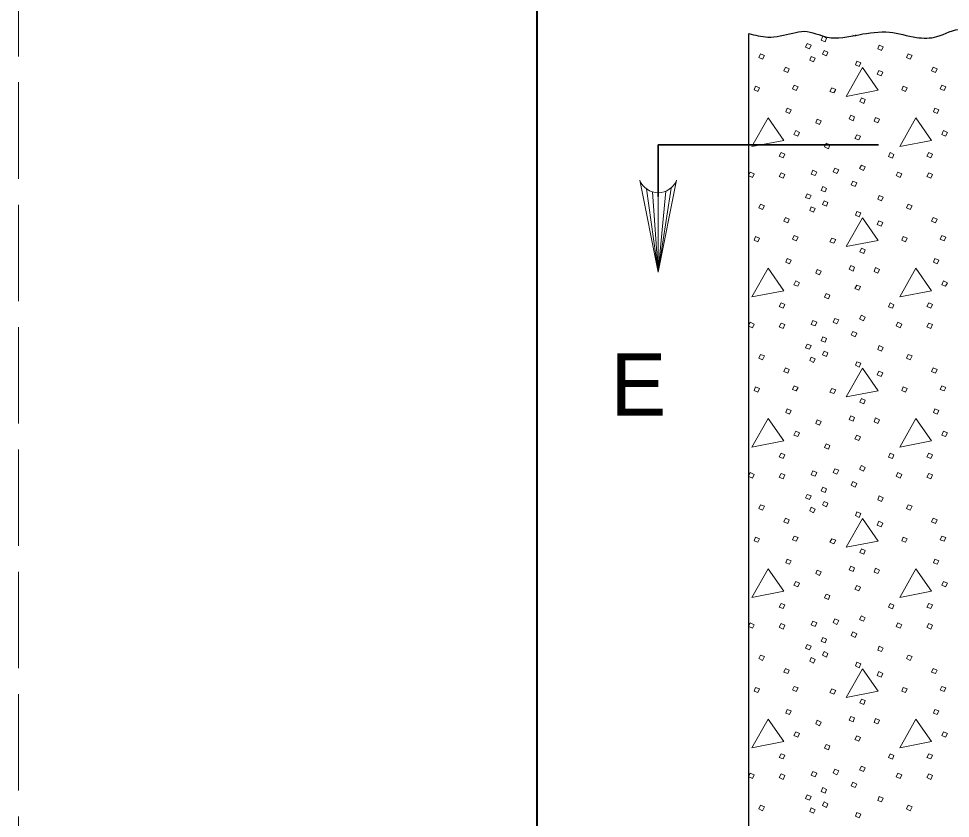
# Model space of a CAD drawing. Extents: x 1036.7 to 1070.7, y 883.9 to 905.9.
# Drawn here: x 1036.673 to 1040.267, y 896.461 to 899.546 of the extents above; entities that cross this region are included whole.
import ezdxf

# ---------------------------------------------------------------- set-up
doc = ezdxf.new("R2010")
doc.units = 0
doc.header["$LTSCALE"] = 0.062
doc.linetypes.add('LONG_DASHED', pattern=[7.5, 6, -1.5])
doc.layers.add('1', color=7, linetype='Continuous', lineweight=13)

msp = doc.modelspace()

# ---------------------------------------------------------------- linework, layer by layer
at = {"layer": '1', "lineweight": 25}
msp.add_line((1039.48992, 893.80992), (1039.48992, 899.48867), dxfattribs=at)
at = {"layer": '1', "lineweight": 35}
for q in [(1039.98967, 899.05975), (1039.14008, 898.85983)]:
    msp.add_line((1039.14008, 899.05975), q, dxfattribs=at)
at = {"layer": '1'}
for p, q in [((1039.48992, 898.94317), (1039.49467, 898.95425)), ((1039.09517, 898.88883), (1039.14008, 898.56833)), ((1039.11742, 898.878), (1039.14008, 898.56833)), ((1039.18958, 898.89258), (1039.14008, 898.56833)), ((1039.16883, 898.88033), (1039.14008, 898.56833)), ((1039.14008, 898.87467), (1039.14008, 898.56833)), ((1039.48992, 898.3635), (1039.49467, 898.37458)), ((1039.48992, 897.78383), (1039.49467, 897.79492)), ((1039.48992, 897.20417), (1039.49467, 897.21525)), ((1039.48992, 896.6245), (1039.49467, 896.63558))]:
    msp.add_line(p, q, dxfattribs=at)
at = {"layer": '1', "linetype": 'LONG_DASHED'}
msp.add_lwpolyline([(1036.67333, 883.90825), (1070.67333, 883.90825), (1070.67333, 905.90825), (1036.67333, 905.90825)], close=True, dxfattribs=at)
at = {"layer": '1', "lineweight": 25}
msp.add_lwpolyline([(1070.17333, 884.40825), (1038.67333, 884.40825), (1038.67333, 905.40825)], dxfattribs=at)
at = {"layer": '1', "lineweight": 40}
msp.add_lwpolyline([(1038.67333, 905.40825), (1070.17333, 905.40825), (1070.17333, 884.40825), (1038.67333, 884.40825)], close=True, dxfattribs=at)
msp.add_lwpolyline([(1038.67333, 905.40825), (1070.17333, 905.40825), (1070.17333, 884.40825), (1038.67333, 884.40825)], close=True, dxfattribs=at)
at = {"layer": '1'}
for points in [[(1039.7745, 899.478), (1039.7895, 899.471), (1039.7835, 899.457), (1039.7685, 899.463)], [(1039.7145, 899.45), (1039.7295, 899.444), (1039.7235, 899.43), (1039.7085, 899.436)], [(1039.99242, 899.444), (1040.00742, 899.437), (1040.00142, 899.423), (1039.98642, 899.429)], [(1039.53458, 899.41), (1039.54958, 899.404), (1039.54258, 899.389), (1039.52758, 899.396)], [(1039.7305, 899.4), (1039.7455, 899.393), (1039.7395, 899.379), (1039.7245, 899.386)], [(1039.7795, 899.423), (1039.7945, 899.416), (1039.7885, 899.402), (1039.7735, 899.409)], [(1040.10433, 899.41), (1040.11933, 899.404), (1040.11233, 899.389), (1040.09733, 899.396)], [(1039.90642, 899.382), (1039.92142, 899.376), (1039.91542, 899.36108), (1039.90042, 899.368)], [(1039.63058, 899.35808), (1039.64558, 899.35208), (1039.63958, 899.33808), (1039.62458, 899.34408)], [(1039.92742, 899.357), (1039.86542, 899.24608), (1039.98842, 899.27008)], [(1039.99142, 899.34608), (1040.00642, 899.33908), (1039.99942, 899.32508), (1039.98442, 899.33108)], [(1040.20033, 899.35808), (1040.21525, 899.35208), (1040.20925, 899.33808), (1040.19433, 899.34408)], [(1039.51558, 899.28508), (1039.53058, 899.27908), (1039.52458, 899.26508), (1039.50958, 899.27108)], [(1039.66458, 899.28908), (1039.6795, 899.28308), (1039.67258, 899.26908), (1039.65758, 899.27508)], [(1039.8095, 899.27908), (1039.8245, 899.27308), (1039.8175, 899.25908), (1039.8025, 899.26508)], [(1040.08533, 899.28508), (1040.10033, 899.27908), (1040.09433, 899.26508), (1040.07933, 899.27108)], [(1040.23425, 899.28908), (1040.24925, 899.28308), (1040.24225, 899.26908), (1040.22725, 899.27508)], [(1039.92342, 899.24008), (1039.93842, 899.23408), (1039.93242, 899.21908), (1039.91742, 899.22608)], [(1039.63758, 899.20017), (1039.65258, 899.19417), (1039.64658, 899.18017), (1039.63158, 899.18617)], [(1040.20733, 899.20017), (1040.22225, 899.19417), (1040.21625, 899.18017), (1040.20133, 899.18617)], [(1039.56358, 899.16317), (1039.50167, 899.05225), (1039.62458, 899.07617)], [(1039.7535, 899.15817), (1039.7685, 899.15117), (1039.7625, 899.13717), (1039.7475, 899.14417)], [(1039.88242, 899.17317), (1039.89742, 899.16717), (1039.89142, 899.15217), (1039.87642, 899.15917)], [(1039.97842, 899.16517), (1039.99342, 899.15817), (1039.98742, 899.14417), (1039.97242, 899.15017)], [(1040.13333, 899.16317), (1040.07133, 899.05225), (1040.19433, 899.07617)], [(1039.67058, 899.11417), (1039.6855, 899.10717), (1039.67858, 899.09317), (1039.66358, 899.09917)], [(1040.24025, 899.11417), (1040.25525, 899.10717), (1040.24825, 899.09317), (1040.23325, 899.09917)], [(1039.90542, 899.09817), (1039.92042, 899.09217), (1039.91342, 899.07817), (1039.89842, 899.08417)], [(1039.7875, 899.06525), (1039.8025, 899.05925), (1039.7965, 899.04425), (1039.7815, 899.05125)], [(1039.61358, 899.02925), (1039.62858, 899.02325), (1039.62158, 899.00925), (1039.60658, 899.01525)], [(1040.03442, 899.02925), (1040.04933, 899.02225), (1040.04333, 899.00825), (1040.02842, 899.01425)], [(1040.18333, 899.02925), (1040.19833, 899.02325), (1040.19133, 899.00925), (1040.17633, 899.01525)], [(1039.8215, 898.96925), (1039.8365, 898.96325), (1039.8295, 898.94825), (1039.8145, 898.95525)], [(1039.92342, 898.98125), (1039.93842, 898.97425), (1039.93142, 898.96025), (1039.91642, 898.96725)], [(1039.61358, 898.95125), (1039.62858, 898.94525), (1039.62158, 898.93025), (1039.60658, 898.93725)], [(1039.7365, 898.96125), (1039.7515, 898.95425), (1039.7455, 898.94025), (1039.7305, 898.94625)], [(1040.06433, 898.95425), (1040.07933, 898.94725), (1040.07333, 898.93325), (1040.05833, 898.94025)], [(1040.18333, 898.95125), (1040.19833, 898.94525), (1040.19133, 898.93025), (1040.17633, 898.93725)], [(1039.7745, 898.89833), (1039.7895, 898.89133), (1039.7835, 898.87733), (1039.7685, 898.88333)], [(1039.89042, 898.91933), (1039.90542, 898.91233), (1039.89942, 898.89833), (1039.88442, 898.90533)], [(1039.7145, 898.87033), (1039.7295, 898.86433), (1039.7235, 898.85033), (1039.7085, 898.85633)], [(1039.99242, 898.86433), (1040.00742, 898.85733), (1040.00142, 898.84333), (1039.98642, 898.84933)], [(1039.53458, 898.83033), (1039.54958, 898.82433), (1039.54258, 898.80933), (1039.52758, 898.81633)], [(1039.7795, 898.84333), (1039.7945, 898.83633), (1039.7885, 898.82233), (1039.7735, 898.82933)], [(1040.10433, 898.83033), (1040.11933, 898.82433), (1040.11233, 898.80933), (1040.09733, 898.81633)], [(1039.7305, 898.82033), (1039.7455, 898.81333), (1039.7395, 898.79933), (1039.7245, 898.80633)], [(1039.90642, 898.80233), (1039.92142, 898.79633), (1039.91542, 898.78133), (1039.90042, 898.78833)], [(1039.63058, 898.77842), (1039.64558, 898.77242), (1039.63958, 898.75842), (1039.62458, 898.76442)], [(1039.92742, 898.77742), (1039.86542, 898.66642), (1039.98842, 898.69042)], [(1039.99142, 898.76642), (1040.00642, 898.75942), (1039.99942, 898.74542), (1039.98442, 898.75142)], [(1040.20033, 898.77842), (1040.21525, 898.77242), (1040.20925, 898.75842), (1040.19433, 898.76442)], [(1039.51558, 898.70542), (1039.53058, 898.69942), (1039.52458, 898.68542), (1039.50958, 898.69142)], [(1039.66458, 898.70942), (1039.6795, 898.70342), (1039.67258, 898.68942), (1039.65758, 898.69542)], [(1039.8095, 898.69942), (1039.8245, 898.69342), (1039.8175, 898.67942), (1039.8025, 898.68542)], [(1040.08533, 898.70542), (1040.10033, 898.69942), (1040.09433, 898.68542), (1040.07933, 898.69142)], [(1040.23425, 898.70942), (1040.24925, 898.70342), (1040.24225, 898.68942), (1040.22725, 898.69542)], [(1039.92342, 898.66042), (1039.93842, 898.65442), (1039.93242, 898.63942), (1039.91742, 898.64642)], [(1039.63758, 898.6205), (1039.65258, 898.6145), (1039.64658, 898.6005), (1039.63158, 898.6065)], [(1040.20733, 898.6205), (1040.22225, 898.6145), (1040.21625, 898.6005), (1040.20133, 898.6065)], [(1039.56358, 898.5835), (1039.50167, 898.47258), (1039.62458, 898.4965)], [(1039.7535, 898.5785), (1039.7685, 898.5715), (1039.7625, 898.5575), (1039.7475, 898.5645)], [(1039.88242, 898.5935), (1039.89742, 898.5875), (1039.89142, 898.5725), (1039.87642, 898.5795)], [(1039.97842, 898.5855), (1039.99342, 898.5785), (1039.98742, 898.5645), (1039.97242, 898.5705)], [(1040.13333, 898.5835), (1040.07133, 898.47258), (1040.19433, 898.4965)], [(1039.67058, 898.5345), (1039.6855, 898.5275), (1039.67858, 898.5135), (1039.66358, 898.5195)], [(1039.90542, 898.5185), (1039.92042, 898.5125), (1039.91342, 898.4985), (1039.89842, 898.5045)], [(1040.24025, 898.5345), (1040.25525, 898.5275), (1040.24825, 898.5135), (1040.23325, 898.5195)], [(1039.7875, 898.48558), (1039.8025, 898.47958), (1039.7965, 898.46458), (1039.7815, 898.47158)], [(1039.61358, 898.44958), (1039.62858, 898.44358), (1039.62158, 898.42958), (1039.60658, 898.43558)], [(1040.03442, 898.44958), (1040.04933, 898.44258), (1040.04333, 898.42858), (1040.02842, 898.43458)], [(1040.18333, 898.44958), (1040.19833, 898.44358), (1040.19133, 898.42958), (1040.17633, 898.43558)], [(1039.92342, 898.40158), (1039.93842, 898.39458), (1039.93142, 898.38058), (1039.91642, 898.38758)], [(1039.61358, 898.37158), (1039.62858, 898.36558), (1039.62158, 898.35058), (1039.60658, 898.35758)], [(1039.7365, 898.38158), (1039.7515, 898.37458), (1039.7455, 898.36058), (1039.7305, 898.36658)], [(1039.8215, 898.38958), (1039.8365, 898.38358), (1039.8295, 898.36858), (1039.8145, 898.37558)], [(1040.06433, 898.37458), (1040.07933, 898.36758), (1040.07333, 898.35358), (1040.05833, 898.36058)], [(1040.18333, 898.37158), (1040.19833, 898.36558), (1040.19133, 898.35058), (1040.17633, 898.35758)], [(1039.89042, 898.33967), (1039.90542, 898.33267), (1039.89942, 898.31867), (1039.88442, 898.32567)], [(1039.7145, 898.29067), (1039.7295, 898.28467), (1039.7235, 898.27067), (1039.7085, 898.27667)], [(1039.7745, 898.31867), (1039.7895, 898.31167), (1039.7835, 898.29767), (1039.7685, 898.30367)], [(1039.99242, 898.28467), (1040.00742, 898.27767), (1040.00142, 898.26367), (1039.98642, 898.26967)], [(1039.53458, 898.25067), (1039.54958, 898.24467), (1039.54258, 898.22967), (1039.52758, 898.23667)], [(1039.7795, 898.26367), (1039.7945, 898.25667), (1039.7885, 898.24267), (1039.7735, 898.24967)], [(1040.10433, 898.25067), (1040.11933, 898.24467), (1040.11233, 898.22967), (1040.09733, 898.23667)], [(1039.7305, 898.24067), (1039.7455, 898.23367), (1039.7395, 898.21967), (1039.7245, 898.22667)], [(1039.90642, 898.22267), (1039.92142, 898.21667), (1039.91542, 898.20167), (1039.90042, 898.20867)], [(1039.63058, 898.19875), (1039.64558, 898.19275), (1039.63958, 898.17875), (1039.62458, 898.18475)], [(1039.92742, 898.19775), (1039.86542, 898.08675), (1039.98842, 898.11075)], [(1039.99142, 898.18675), (1040.00642, 898.17975), (1039.99942, 898.16575), (1039.98442, 898.17175)], [(1040.20033, 898.19875), (1040.21525, 898.19275), (1040.20925, 898.17875), (1040.19433, 898.18475)], [(1039.51558, 898.12575), (1039.53058, 898.11975), (1039.52458, 898.10575), (1039.50958, 898.11175)], [(1039.66458, 898.12975), (1039.6795, 898.12375), (1039.67258, 898.10975), (1039.65758, 898.11575)], [(1039.8095, 898.11975), (1039.8245, 898.11375), (1039.8175, 898.09975), (1039.8025, 898.10575)], [(1040.08533, 898.12575), (1040.10033, 898.11975), (1040.09433, 898.10575), (1040.07933, 898.11175)], [(1040.23425, 898.12975), (1040.24925, 898.12375), (1040.24225, 898.10975), (1040.22725, 898.11575)], [(1039.92342, 898.08075), (1039.93842, 898.07475), (1039.93242, 898.05975), (1039.91742, 898.06675)], [(1039.63758, 898.04083), (1039.65258, 898.03483), (1039.64658, 898.02083), (1039.63158, 898.02683)], [(1040.20733, 898.04083), (1040.22225, 898.03483), (1040.21625, 898.02083), (1040.20133, 898.02683)], [(1039.56358, 898.00383), (1039.50167, 897.89292), (1039.62458, 897.91683)], [(1039.7535, 897.99883), (1039.7685, 897.99183), (1039.7625, 897.97783), (1039.7475, 897.98483)], [(1039.88242, 898.01383), (1039.89742, 898.00783), (1039.89142, 897.99283), (1039.87642, 897.99983)], [(1039.97842, 898.00583), (1039.99342, 897.99883), (1039.98742, 897.98483), (1039.97242, 897.99083)], [(1040.13333, 898.00383), (1040.07133, 897.89292), (1040.19433, 897.91683)], [(1039.67058, 897.95483), (1039.6855, 897.94783), (1039.67858, 897.93383), (1039.66358, 897.93983)], [(1039.90542, 897.93883), (1039.92042, 897.93283), (1039.91342, 897.91883), (1039.89842, 897.92483)], [(1040.24025, 897.95483), (1040.25525, 897.94783), (1040.24825, 897.93383), (1040.23325, 897.93983)], [(1039.7875, 897.90592), (1039.8025, 897.89992), (1039.7965, 897.88492), (1039.7815, 897.89192)], [(1039.61358, 897.86992), (1039.62858, 897.86392), (1039.62158, 897.84992), (1039.60658, 897.85592)], [(1040.03442, 897.86992), (1040.04933, 897.86292), (1040.04333, 897.84892), (1040.02842, 897.85492)], [(1040.18333, 897.86992), (1040.19833, 897.86392), (1040.19133, 897.84992), (1040.17633, 897.85592)], [(1039.92342, 897.82192), (1039.93842, 897.81492), (1039.93142, 897.80092), (1039.91642, 897.80792)], [(1039.61358, 897.79192), (1039.62858, 897.78592), (1039.62158, 897.77092), (1039.60658, 897.77792)], [(1039.7365, 897.80192), (1039.7515, 897.79492), (1039.7455, 897.78092), (1039.7305, 897.78692)], [(1039.8215, 897.80992), (1039.8365, 897.80392), (1039.8295, 897.78892), (1039.8145, 897.79592)], [(1040.06433, 897.79492), (1040.07933, 897.78792), (1040.07333, 897.77392), (1040.05833, 897.78092)], [(1040.18333, 897.79192), (1040.19833, 897.78592), (1040.19133, 897.77092), (1040.17633, 897.77792)], [(1039.89042, 897.76), (1039.90542, 897.753), (1039.89942, 897.739), (1039.88442, 897.746)], [(1039.7145, 897.711), (1039.7295, 897.705), (1039.7235, 897.691), (1039.7085, 897.697)], [(1039.7745, 897.739), (1039.7895, 897.732), (1039.7835, 897.718), (1039.7685, 897.724)], [(1039.7795, 897.684), (1039.7945, 897.677), (1039.7885, 897.663), (1039.7735, 897.67)], [(1039.99242, 897.705), (1040.00742, 897.698), (1040.00142, 897.684), (1039.98642, 897.69)], [(1039.53458, 897.671), (1039.54958, 897.665), (1039.54258, 897.65), (1039.52758, 897.657)], [(1039.7305, 897.661), (1039.7455, 897.654), (1039.7395, 897.64), (1039.7245, 897.647)], [(1039.90642, 897.643), (1039.92142, 897.637), (1039.91542, 897.62208), (1039.90042, 897.629)], [(1040.10433, 897.671), (1040.11933, 897.665), (1040.11233, 897.65), (1040.09733, 897.657)], [(1039.63058, 897.61908), (1039.64558, 897.61308), (1039.63958, 897.59908), (1039.62458, 897.60508)], [(1039.92742, 897.61808), (1039.86542, 897.50708), (1039.98842, 897.53108)], [(1039.99142, 897.60708), (1040.00642, 897.60008), (1039.99942, 897.58608), (1039.98442, 897.59208)], [(1040.20033, 897.61908), (1040.21525, 897.61308), (1040.20925, 897.59908), (1040.19433, 897.60508)], [(1039.51558, 897.54608), (1039.53058, 897.54008), (1039.52458, 897.52608), (1039.50958, 897.53208)], [(1039.66458, 897.55008), (1039.6795, 897.54408), (1039.67258, 897.53008), (1039.65758, 897.53608)], [(1039.8095, 897.54008), (1039.8245, 897.53408), (1039.8175, 897.52008), (1039.8025, 897.52608)], [(1040.08533, 897.54608), (1040.10033, 897.54008), (1040.09433, 897.52608), (1040.07933, 897.53208)], [(1040.23425, 897.55008), (1040.24925, 897.54408), (1040.24225, 897.53008), (1040.22725, 897.53608)], [(1039.92342, 897.50108), (1039.93842, 897.49508), (1039.93242, 897.48017), (1039.91742, 897.48708)], [(1039.63758, 897.46117), (1039.65258, 897.45517), (1039.64658, 897.44117), (1039.63158, 897.44717)], [(1040.20733, 897.46117), (1040.22225, 897.45517), (1040.21625, 897.44117), (1040.20133, 897.44717)], [(1039.56358, 897.42417), (1039.50167, 897.31325), (1039.62458, 897.33717)], [(1039.88242, 897.43417), (1039.89742, 897.42817), (1039.89142, 897.41317), (1039.87642, 897.42017)], [(1039.97842, 897.42617), (1039.99342, 897.41917), (1039.98742, 897.40517), (1039.97242, 897.41117)], [(1040.13333, 897.42417), (1040.07133, 897.31325), (1040.19433, 897.33717)], [(1039.7535, 897.41917), (1039.7685, 897.41217), (1039.7625, 897.39817), (1039.7475, 897.40517)], [(1039.67058, 897.37517), (1039.6855, 897.36817), (1039.67858, 897.35417), (1039.66358, 897.36017)], [(1039.90542, 897.35917), (1039.92042, 897.35317), (1039.91342, 897.33917), (1039.89842, 897.34517)], [(1040.24025, 897.37517), (1040.25525, 897.36817), (1040.24825, 897.35417), (1040.23325, 897.36017)], [(1039.7875, 897.32625), (1039.8025, 897.32025), (1039.7965, 897.30525), (1039.7815, 897.31225)], [(1039.61358, 897.29025), (1039.62858, 897.28425), (1039.62158, 897.27025), (1039.60658, 897.27625)], [(1040.03442, 897.29025), (1040.04933, 897.28325), (1040.04333, 897.26925), (1040.02842, 897.27525)], [(1040.18333, 897.29025), (1040.19833, 897.28425), (1040.19133, 897.27025), (1040.17633, 897.27625)], [(1039.92342, 897.24225), (1039.93842, 897.23525), (1039.93142, 897.22125), (1039.91642, 897.22825)], [(1039.61358, 897.21225), (1039.62858, 897.20625), (1039.62158, 897.19125), (1039.60658, 897.19825)], [(1039.7365, 897.22225), (1039.7515, 897.21525), (1039.7455, 897.20125), (1039.7305, 897.20725)], [(1039.8215, 897.23025), (1039.8365, 897.22425), (1039.8295, 897.20925), (1039.8145, 897.21625)], [(1040.06433, 897.21525), (1040.07933, 897.20825), (1040.07333, 897.19425), (1040.05833, 897.20125)], [(1040.18333, 897.21225), (1040.19833, 897.20625), (1040.19133, 897.19125), (1040.17633, 897.19825)], [(1039.89042, 897.18033), (1039.90542, 897.17333), (1039.89942, 897.15933), (1039.88442, 897.16633)], [(1039.7745, 897.15933), (1039.7895, 897.15233), (1039.7835, 897.13833), (1039.7685, 897.14433)], [(1039.7145, 897.13133), (1039.7295, 897.12533), (1039.7235, 897.11133), (1039.7085, 897.11733)], [(1039.7795, 897.10433), (1039.7945, 897.09733), (1039.7885, 897.08333), (1039.7735, 897.09033)], [(1039.99242, 897.12533), (1040.00742, 897.11833), (1040.00142, 897.10433), (1039.98642, 897.11033)], [(1039.53458, 897.09133), (1039.54958, 897.08533), (1039.54258, 897.07033), (1039.52758, 897.07733)], [(1039.7305, 897.08133), (1039.7455, 897.07433), (1039.7395, 897.06033), (1039.7245, 897.06733)], [(1039.90642, 897.06333), (1039.92142, 897.05733), (1039.91542, 897.04242), (1039.90042, 897.04933)], [(1040.10433, 897.09133), (1040.11933, 897.08533), (1040.11233, 897.07033), (1040.09733, 897.07733)], [(1039.63058, 897.03942), (1039.64558, 897.03342), (1039.63958, 897.01942), (1039.62458, 897.02542)], [(1039.92742, 897.03842), (1039.86542, 896.92742), (1039.98842, 896.95142)], [(1039.99142, 897.02742), (1040.00642, 897.02042), (1039.99942, 897.00642), (1039.98442, 897.01242)], [(1040.20033, 897.03942), (1040.21525, 897.03342), (1040.20925, 897.01942), (1040.19433, 897.02542)], [(1039.51558, 896.96642), (1039.53058, 896.96042), (1039.52458, 896.94642), (1039.50958, 896.95242)], [(1039.66458, 896.97042), (1039.6795, 896.96442), (1039.67258, 896.95042), (1039.65758, 896.95642)], [(1039.8095, 896.96042), (1039.8245, 896.95442), (1039.8175, 896.94042), (1039.8025, 896.94642)], [(1040.08533, 896.96642), (1040.10033, 896.96042), (1040.09433, 896.94642), (1040.07933, 896.95242)], [(1040.23425, 896.97042), (1040.24925, 896.96442), (1040.24225, 896.95042), (1040.22725, 896.95642)], [(1039.92342, 896.92142), (1039.93842, 896.91542), (1039.93242, 896.9005), (1039.91742, 896.90742)], [(1039.63758, 896.8815), (1039.65258, 896.8755), (1039.64658, 896.8615), (1039.63158, 896.8675)], [(1039.88242, 896.8545), (1039.89742, 896.8485), (1039.89142, 896.8335), (1039.87642, 896.8405)], [(1039.97842, 896.8465), (1039.99342, 896.8395), (1039.98742, 896.8255), (1039.97242, 896.8315)], [(1040.20733, 896.8815), (1040.22225, 896.8755), (1040.21625, 896.8615), (1040.20133, 896.8675)], [(1039.56358, 896.8445), (1039.50167, 896.73358), (1039.62458, 896.7575)], [(1039.7535, 896.8395), (1039.7685, 896.8325), (1039.7625, 896.8185), (1039.7475, 896.8255)], [(1040.13333, 896.8445), (1040.07133, 896.73358), (1040.19433, 896.7575)], [(1039.67058, 896.7955), (1039.6855, 896.7885), (1039.67858, 896.7745), (1039.66358, 896.7805)], [(1039.90542, 896.7795), (1039.92042, 896.7735), (1039.91342, 896.7595), (1039.89842, 896.7655)], [(1040.24025, 896.7955), (1040.25525, 896.7885), (1040.24825, 896.7745), (1040.23325, 896.7805)], [(1039.7875, 896.74658), (1039.8025, 896.74058), (1039.7965, 896.72558), (1039.7815, 896.73258)], [(1039.61358, 896.71058), (1039.62858, 896.70458), (1039.62158, 896.69058), (1039.60658, 896.69658)], [(1040.03442, 896.71058), (1040.04933, 896.70358), (1040.04333, 896.68958), (1040.02842, 896.69558)], [(1040.18333, 896.71058), (1040.19833, 896.70458), (1040.19133, 896.69058), (1040.17633, 896.69658)], [(1039.61358, 896.63258), (1039.62858, 896.62658), (1039.62158, 896.61167), (1039.60658, 896.61858)], [(1039.7365, 896.64258), (1039.7515, 896.63558), (1039.7455, 896.62158), (1039.7305, 896.62758)], [(1039.8215, 896.65058), (1039.8365, 896.64458), (1039.8295, 896.62958), (1039.8145, 896.63658)], [(1039.92342, 896.66258), (1039.93842, 896.65558), (1039.93142, 896.64158), (1039.91642, 896.64858)], [(1040.06433, 896.63558), (1040.07933, 896.62858), (1040.07333, 896.61458), (1040.05833, 896.62158)], [(1040.18333, 896.63258), (1040.19833, 896.62658), (1040.19133, 896.61167), (1040.17633, 896.61858)], [(1039.89042, 896.60067), (1039.90542, 896.59367), (1039.89942, 896.57967), (1039.88442, 896.58667)], [(1039.7745, 896.57967), (1039.7895, 896.57267), (1039.7835, 896.55867), (1039.7685, 896.56467)], [(1039.7145, 896.55167), (1039.7295, 896.54567), (1039.7235, 896.53167), (1039.7085, 896.53767)], [(1039.7795, 896.52467), (1039.7945, 896.51767), (1039.7885, 896.50367), (1039.7735, 896.51067)], [(1039.99242, 896.54567), (1040.00742, 896.53867), (1040.00142, 896.52467), (1039.98642, 896.53067)], [(1039.53458, 896.51167), (1039.54958, 896.50567), (1039.54258, 896.49067), (1039.52758, 896.49767)], [(1039.7305, 896.50167), (1039.7455, 896.49467), (1039.7395, 896.48067), (1039.7245, 896.48767)], [(1040.10433, 896.51167), (1040.11933, 896.50567), (1040.11233, 896.49067), (1040.09733, 896.49767)], [(1039.90642, 896.48367), (1039.92142, 896.47767), (1039.91542, 896.46275), (1039.90042, 896.46967)]]:
    msp.add_lwpolyline(points, close=True, dxfattribs=at)
for points in [[(1039.9015, 899.48292), (1039.89942, 899.478), (1039.89067, 899.48208)], [(1039.49467, 898.95425), (1039.50958, 898.94725), (1039.50358, 898.93325), (1039.48992, 898.93967)], [(1039.21083, 898.92233), (1039.14008, 898.56833), (1039.06925, 898.92233)], [(1039.49467, 898.37458), (1039.50958, 898.36758), (1039.50358, 898.35358), (1039.48992, 898.36)], [(1039.49467, 897.79492), (1039.50958, 897.78792), (1039.50358, 897.77392), (1039.48992, 897.78033)], [(1039.49467, 897.21525), (1039.50958, 897.20825), (1039.50358, 897.19425), (1039.48992, 897.20067)], [(1039.49467, 896.63558), (1039.50958, 896.62858), (1039.50358, 896.61458), (1039.48992, 896.621)]]:
    msp.add_lwpolyline(points, dxfattribs=at)
msp.add_arc((1039.13997, 898.95092), 0.0764, 202.08782, 337.91395, dxfattribs=at)
at = {"layer": '1', "lineweight": 25}
msp.add_spline([(1039.48992, 899.48867), (1039.56225, 899.47492), (1039.65908, 899.49033), (1039.70367, 899.49708), (1039.79208, 899.47442), (1039.91375, 899.48392), (1040.03217, 899.4935), (1040.13583, 899.47375), (1040.215, 899.47642), (1040.31, 899.504), (1040.34283, 899.49733), (1040.37917, 899.50008)], degree=3, dxfattribs=at)

# ---------------------------------------------------------------- texts
at = {"layer": '1'}
msp.add_text('E', height=0.24, dxfattribs=at).set_placement((1038.95633, 898.01508))

doc.saveas('drawing.dxf')
